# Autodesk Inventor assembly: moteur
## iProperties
Shininess: 64.0
Length Units: 11269
Angle Units: 11279
Time Units: 11290
Mass Units: 11283
Length Display Precision: 3
Angle Display Precision: 2
Compacted: True
Created: 2004-05
Part Number: moteur
Document SubType Name: Assembly
Designer: David
Density: 0.0
Volumn: 0.0
Area: 0.0
PropertySet Name: Model Information
Control State: 0
Master: False
Checked Out: False
Author: David
